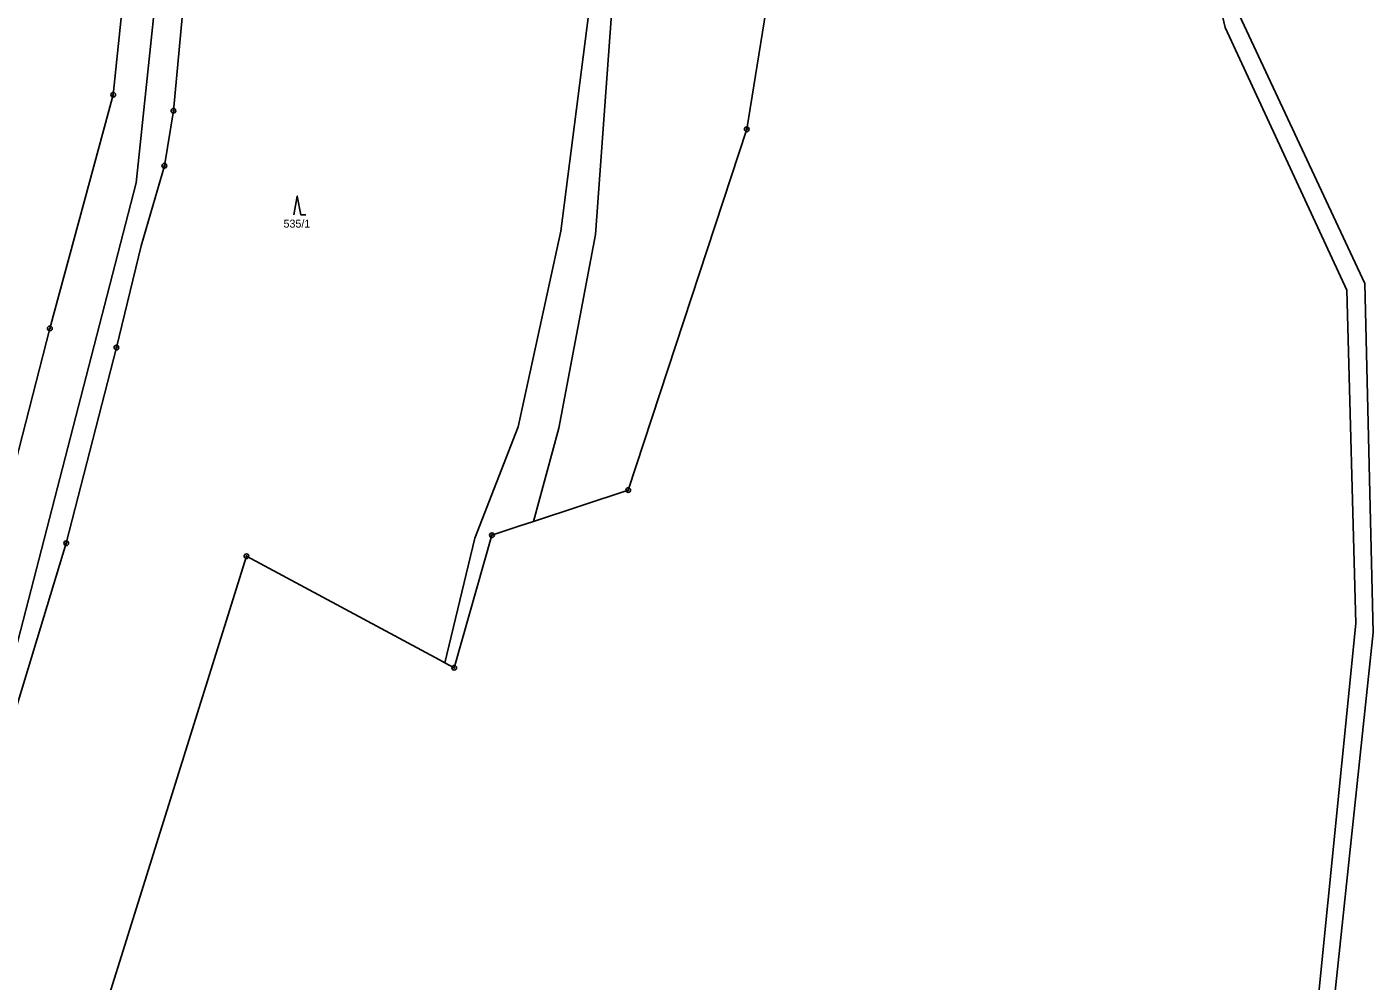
# Model space of a CAD drawing. Extents: x -547623 to -538651, y -1096714 to -1086522.
# Drawn here: x -546016.7 to -545730.8, y -1092406 to -1092203.4 of the extents above; entities that cross this region are included whole.
import ezdxf

# ---------------------------------------------------------------- set-up
doc = ezdxf.new("R2010")
doc.units = 0
for name, color, linetype in [('Vrstva 1', 7, 'Continuous'), ('Vrstva 25', 7, 'Continuous'), ('Vrstva 41', 7, 'Continuous'), ('Vrstva 52', 7, 'Continuous'), ('Vrstva 83', 7, 'Continuous'), ('Vrstva 86', 7, 'Continuous')]:
    doc.layers.add(name, color=color, linetype=linetype)

msp = doc.modelspace()

# ---------------------------------------------------------------- linework, layer by layer
at = {"layer": 'Vrstva 1'}
for points in [[(-545762.2, -1092203.47), (-545771.45, -1092163.93)], [(-545998.36, -1092217.78), (-545993.37, -1092169.37)], [(-545980.89, -1092170.8), (-545985.6, -1092221.18)], [(-545895.94, -1092247.48), (-545891.01, -1092179.14)], [(-545903.29, -1092246.77), (-545897.07, -1092198.1)], [(-545759.73, -1092199.71), (-545732.55, -1092257.84)], [(-545736.38, -1092259.28), (-545762.2, -1092203.47)], [(-546011.84, -1092267.42), (-545998.36, -1092217.78)], [(-545985.6, -1092221.18), (-545987.52, -1092232.84)], [(-545987.52, -1092232.84), (-545992.46, -1092249.83)], [(-545912.34, -1092288.33), (-545903.29, -1092246.77)], [(-545903.7, -1092288.56), (-545895.94, -1092247.48)], [(-545992.46, -1092249.83), (-545997.69, -1092271.48)], [(-545732.55, -1092257.84), (-545730.79, -1092332.02)], [(-545734.45, -1092330.08), (-545736.38, -1092259.28)], [(-546022, -1092307.19), (-546011.84, -1092267.42)], [(-545997.69, -1092271.48), (-546008.36, -1092313.04)], [(-545921.54, -1092311.98), (-545912.34, -1092288.33)], [(-545903.7, -1092288.56), (-545909.11, -1092308.4)], [(-546008.36, -1092313.04), (-546021.91, -1092357.59)], [(-545921.54, -1092311.98), (-545927.92, -1092338.43)], [(-545743.38, -1092419.1), (-545734.45, -1092330.08)], [(-545730.79, -1092332.02), (-545739.97, -1092418.85)]]:
    msp.add_lwpolyline(points, dxfattribs=at)
at = {"layer": 'Vrstva 25'}
msp.add_lwpolyline([(-545960, -1092243.3), (-545959.3, -1092239.3), (-545958.5, -1092243.3), (-545957.5, -1092243.3)], dxfattribs=at)
at = {"layer": 'Vrstva 41'}
for points in [[(-545863.82, -1092225.12), (-545852.07, -1092152.21)], [(-545863.82, -1092225.12), (-545852.07, -1092152.21)], [(-545888.98, -1092301.73), (-545863.82, -1092225.12)], [(-545888.98, -1092301.73), (-545863.82, -1092225.12)], [(-545909.11, -1092308.4), (-545888.98, -1092301.73)], [(-545909.11, -1092308.4), (-545888.98, -1092301.73)], [(-545917.93, -1092311.32), (-545912.21, -1092309.43)], [(-545917.93, -1092311.32), (-545912.21, -1092309.43)], [(-545912.21, -1092309.43), (-545909.11, -1092308.4)], [(-545912.21, -1092309.43), (-545909.11, -1092308.4)], [(-545925.95, -1092339.49), (-545917.93, -1092311.32)], [(-545925.95, -1092339.49), (-545917.93, -1092311.32)], [(-546006.74, -1092433.01), (-545970.08, -1092315.78)], [(-546006.74, -1092433.01), (-545970.08, -1092315.78)], [(-545970.08, -1092315.78), (-545929.1, -1092337.8)], [(-545970.08, -1092315.78), (-545929.1, -1092337.8)], [(-545929.1, -1092337.8), (-545927.92, -1092338.43)], [(-545929.1, -1092337.8), (-545927.92, -1092338.43)], [(-545927.92, -1092338.43), (-545925.95, -1092339.49)], [(-545927.92, -1092338.43), (-545925.95, -1092339.49)]]:
    msp.add_lwpolyline(points, dxfattribs=at)
at = {"layer": 'Vrstva 52'}
msp.add_lwpolyline([(-546058.01, -1092480.59), (-546048, -1092436), (-546026.5, -1092364), (-545993.5, -1092236.5), (-545979.5, -1092103), (-545974.29, -1092099.39), (-545974.76, -1092106.08), (-545965.89, -1092099.89), (-545952.68, -1092076.83), (-545945.77, -1092069.17), (-545929.46, -1092056.66), (-545907.78, -1092046.24), (-545907.16, -1092046.43), (-545900.5, -1092048.5), (-545891.34, -1092056.22), (-545882.78, -1092063.44), (-545875, -1092070), (-545874.34, -1092071.02), (-545873.17, -1092072.82), (-545871.39, -1092075.56), (-545856.5, -1092098.5)], dxfattribs=at)
at = {"layer": 'Vrstva 83'}
for centre, radius in [((-545998.36, -1092217.78), 0.5), ((-545998.36, -1092217.78), 0.1), ((-545985.6, -1092221.18), 0.5), ((-545985.6, -1092221.18), 0.1), ((-545863.82, -1092225.12), 0.5), ((-545863.82, -1092225.12), 0.1), ((-545987.52, -1092232.84), 0.5), ((-545987.52, -1092232.84), 0.1), ((-546011.84, -1092267.42), 0.5), ((-546011.84, -1092267.42), 0.1), ((-545997.69, -1092271.48), 0.5), ((-545997.69, -1092271.48), 0.1), ((-545888.98, -1092301.73), 0.5), ((-545888.98, -1092301.73), 0.1), ((-546008.36, -1092313.04), 0.5), ((-546008.36, -1092313.04), 0.1), ((-545917.93, -1092311.32), 0.5), ((-545917.93, -1092311.32), 0.1), ((-545970.08, -1092315.78), 0.5), ((-545970.08, -1092315.78), 0.1), ((-545925.95, -1092339.49), 0.5), ((-545925.95, -1092339.49), 0.1)]:
    msp.add_circle(centre, radius, dxfattribs=at)

# ---------------------------------------------------------------- texts
at = {"layer": 'Vrstva 86'}
msp.add_text('535/1', height=1.7, dxfattribs=at).set_placement((-545962.21, -1092246))

doc.saveas('drawing.dxf')
